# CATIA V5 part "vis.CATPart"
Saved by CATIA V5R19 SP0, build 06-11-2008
Part number: vis CH102008
Bounding box of the stored display mesh (mm): x 0 to 10, y -1.9 to 1.9, z -1.9 to 1.9
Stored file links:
  G:\project guitar elect\vis.CATPart
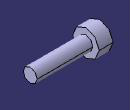
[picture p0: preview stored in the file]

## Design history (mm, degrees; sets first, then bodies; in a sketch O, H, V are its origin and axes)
Body1 (main body)
  Sketch1 on yz-plane, origin (0, 0, 0), H (0, 1, 0), V (0, 0, 1)
    circle A1 centre (0, 0) radius 1.9
    radius A1 = 1.9
  Pad1: profile Sketch1, direction (1, 0, 0), length 2
  Sketch2 on end face of Pad1, origin (2, 0, 0), H (0, 1, 0), V (0, 0, 1)
    circle A1 centre (0, 0) radius 1
    radius A1 = 1
  Pad2: profile Sketch2, direction (1, 0, 0), length 8
  Sketch3 on start face of Pad1, origin (0, 0, 0), H (0, -1, 0), V (0, 0, 1)
    point P1 (0.6491, -0.3757)
    line L1 (0.6491, -0.3757) -> (0.6491, 0.3757)
    point P2 (0.6491, 0.3757)
    line L2 (0.6491, 0.3757) -> (0, 0.75)
    point P3 (0, 0.75)
    line L3 (0.6491, -0.3757) -> (0, -0.75)
    point P4 (0, -0.75)
    axis line L4 (0, 1.1732) -> (0, -1.4036)
    point P5 (0, 1.1732)
    point P7 (0, -0.75)
    point P8 (-0.6491, -0.3757)
    line L5 (-0.6491, -0.3757) -> (0, -0.75)
    point P9 (-0.6491, 0.3757)
    line L6 (-0.6491, -0.3757) -> (-0.6491, 0.3757)
    point P10 (0, 0.75)
    line L7 (-0.6491, 0.3757) -> (0, 0.75)
    vertical: L1 V, L4 V
    coincidence: P3 V, P4 V, P5 V, P3 P10, P4 P7
    symmetry: P4 P7 L4, P1 P8 L4, L3 L5 L4, P2 P9 L4, L1 L6 L4, P3 P10 L4, L2 L7 L4
  Pocket1: profile Sketch3, direction (1, 0, 0), length 1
